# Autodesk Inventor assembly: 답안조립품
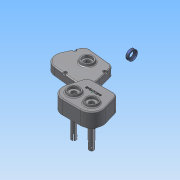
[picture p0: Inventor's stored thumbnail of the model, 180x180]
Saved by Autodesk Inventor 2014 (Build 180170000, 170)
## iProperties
Created: 2014-12
Part Number: 답안조립품
Document SubType Name: Assembly
Designer: user
Author: user
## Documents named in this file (11)
- C:\Users\user\Desktop\441208V1035\답안조립품.iam
- C:\Users\user\Desktop\441208V1035\본체.ipt
- C:\Users\user\Desktop\441208V1035\메인축.ipt
- C:\Users\user\Desktop\441208V1035\서브축.ipt
- C:\Users\user\Desktop\441208V1035\커버.ipt
- C:\Users\user\Desktop\441208V1035\오일시일-D-17.ipt
- C:\Users\user\Desktop\441208V1035\베어링- 6203.ipt
- C:\Users\user\Desktop\441208V1035\키5x5.ipt
- C:\Users\user\Desktop\441208V1035\메인기어.ipt
- C:\Users\user\Desktop\441208V1035\베어링- 6202.ipt
- C:\Users\user\Desktop\441208V1035\서브기어.ipt
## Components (7 placed, 3 different names)
1. KS B 2804 D D - 17 30 8:1
2. KS B 2023 6203 - 17 x 40 x 12:1
3. KS B 2023 6202 - 15 x 35 x 11:1
4. KS B 2023 6202 - 15 x 35 x 11:2
5. KS B 2023 6202 - 15 x 35 x 11:3
6. KS B 2023 6202 - 15 x 35 x 11:4
7. KS B 2023 6203 - 17 x 40 x 12:2
